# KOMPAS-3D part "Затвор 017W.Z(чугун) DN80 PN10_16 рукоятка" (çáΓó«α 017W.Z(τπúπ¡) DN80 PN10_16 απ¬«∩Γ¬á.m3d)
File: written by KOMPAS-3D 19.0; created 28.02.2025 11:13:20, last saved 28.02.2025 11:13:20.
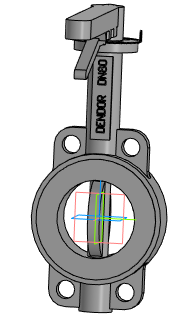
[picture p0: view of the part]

Document properties: Автор: Евгений; Полное имя файла: Затвор 017W.Z(чугун) DN80 PN10_16 рукоятка.a3d

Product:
- Part/product: Затвор 017W.Z(чугун) DN80 PN10_16 рукоятка
    Масса: 6.53716

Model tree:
1. Операция без истории:1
